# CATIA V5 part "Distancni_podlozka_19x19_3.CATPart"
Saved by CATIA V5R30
Part number: Distancni_podlozka_19x19_3
Definition: EH 6281_19x19
Nomenclature: EH 6281_19x19
Source: Unknown
Description: PART--DESC
Bounding box of the stored display mesh (mm): x 120 to 139, y 9.01 to 27.99, z 20.7 to 39.7
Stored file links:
  E:\Bakalarka\Model\Forma_v7\Distancni_podlozka_19x19_3.CATPart
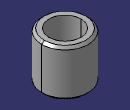
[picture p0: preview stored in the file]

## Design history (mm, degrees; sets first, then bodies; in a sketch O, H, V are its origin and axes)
Body1 "MANIFOLD_SOLID_BREP #3730" (main body)
  Solid1: solid without history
